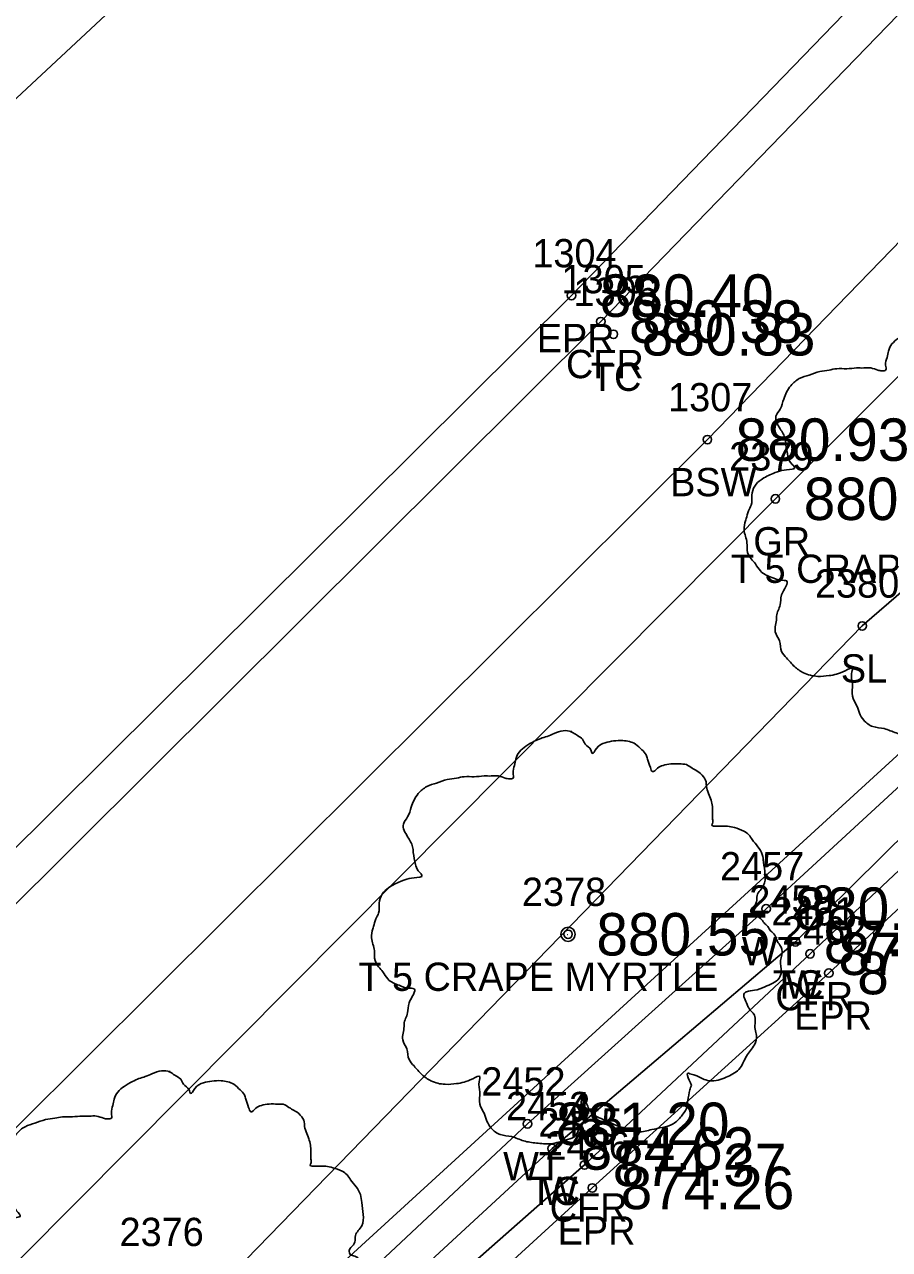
# Model space of a CAD drawing. Extents: x 1622501 to 1626664, y 1117816 to 1121579.
# Drawn here: x 1623704.15 to 1623734.7, y 1118952.01 to 1118995.3 of the extents above; entities that cross this region are included whole.
import ezdxf

# ---------------------------------------------------------------- set-up
doc = ezdxf.new("R2010")
doc.units = 0
for name, color, linetype in [('RD_EX_BldgApp', 7, 'Continuous'), ('RD_EX_Conc', 7, 'Continuous'), ('RD_EX_Conc_txCode', 7, 'Continuous'), ('RD_EX_Fence_Other', 7, 'Continuous'), ('RD_EX_GuardRail', 7, 'Continuous'), ('RD_EX_GuardRail_txCode', 7, 'Continuous'), ('RD_EX_Misc', 7, 'Continuous'), ('RD_EX_Misc_txCode', 7, 'Continuous'), ('RD_EX_Road', 7, 'Continuous'), ('RD_EX_Road_txCode', 7, 'Continuous'), ('RD_EX_TX_Conc_ELEV', 7, 'Continuous'), ('RD_EX_TX_GuardRail_ELEV', 7, 'Continuous'), ('RD_EX_TX_Misc_ELEV', 7, 'Continuous'), ('RD_EX_TX_Road_ELEV', 7, 'Continuous'), ('RD_EX_TX_VEG_ELEV', 7, 'Continuous'), ('RD_EX_VEG', 7, 'Continuous'), ('RD_EX_VEG_txCode', 7, 'Continuous'), ('RD_HC_Cl', 7, 'Continuous'), ('RD_SMD_Locator', 7, 'Continuous')]:
    doc.layers.add(name, color=color, linetype=linetype)

msp = doc.modelspace()

# ---------------------------------------------------------------- linework, layer by layer
at = {"layer": 'RD_EX_BldgApp'}
msp.add_lwpolyline([(1623721.004, 1118923.881), (1623713.492, 1118931.399), (1623708.579, 1118936.802), (1623708.092, 1118940.743), (1623709.133, 1118942.964), (1623722.787, 1118955.582), (1623731.375, 1118962.881), (1623739.462, 1118970.878), (1623747.819, 1118978.398), (1623756.721, 1118986.256), (1623762.191, 1118991.565), (1623766.243, 1118995.292)], dxfattribs=at)
at = {"layer": 'RD_EX_Conc'}
for points in [[(1623723.663, 1118851.276), (1623685.686, 1118891.781), (1623680.278, 1118899.276), (1623678.543, 1118902.667), (1623678.543, 1118902.667), (1623675.573, 1118911.952), (1623675.054, 1118920.354), (1623676.566, 1118930.331), (1623679.225, 1118937.184), (1623684.435, 1118944.641), (1623689.976, 1118950.418), (1623724.501, 1118984.8), (1623759.009, 1119020.42), (1623793.698, 1119055.906), (1623829.35, 1119090.862), (1623865.612, 1119125.129), (1623901.916, 1119159.181), (1623933.224, 1119188.498)], [(1623676.299, 1118912.014), (1623681.213, 1118913.011), (1623680.576, 1118920.41), (1623681.86, 1118928.773), (1623684.243, 1118934.734), (1623688.548, 1118940.788), (1623694.147, 1118946.67), (1623728.265, 1118980.628), (1623762.622, 1119016.068), (1623797.565, 1119051.919), (1623833.104, 1119086.631), (1623869.148, 1119120.8), (1623905.547, 1119154.999), (1623936.969, 1119184.346), (1623933.79, 1119188.026)], [(1623731.27, 1118881.874), (1623724.208, 1118889.844), (1623728.268, 1118894.109), (1623731.921, 1118899.236), (1623734.19, 1118906.762), (1623732.955, 1118915.502), (1623727.506, 1118923.921), (1623710.242, 1118942.93), (1623723.924, 1118955.001), (1623731.892, 1118962.462), (1623739.934, 1118970.016), (1623748.093, 1118977.566), (1623756.653, 1118985.283), (1623766.427, 1118974.182), (1623768.958, 1118972.879), (1623771.85, 1118973.67), (1623773.97, 1118975.964), (1623773.97, 1118975.964), (1623773.559, 1118979.96), (1623763.52, 1118991.319), (1623776.374, 1119003.735), (1623808.841, 1119034.289)]]:
    msp.add_lwpolyline(points, dxfattribs=at)
at = {"layer": 'RD_EX_Fence_Other'}
msp.add_lwpolyline([(1623719.865, 1118922.561), (1623707.713, 1118935.278), (1623705.87, 1118941.129), (1623709.567, 1118946.223), (1623737.438, 1118971.731), (1623764.682, 1118996.227)], dxfattribs=at)
at = {"layer": 'RD_EX_GuardRail'}
msp.add_lwpolyline([(1623683.102, 1118919.005), (1623685.557, 1118930.82), (1623696.428, 1118944.075), (1623730.666, 1118978.537), (1623766.322, 1119014.094)], dxfattribs=at)
at = {"layer": 'RD_EX_Misc'}
msp.add_lwpolyline([(1623720.394, 1118923.404), (1623713.005, 1118930.814), (1623708.177, 1118936.136), (1623707.246, 1118941.456), (1623708.502, 1118943.888), (1623721.912, 1118956.453), (1623730.341, 1118964.055), (1623738.647, 1118971.704), (1623746.964, 1118979.27), (1623755.423, 1118986.8), (1623761.506, 1118992.463), (1623765.64, 1118996.049)], dxfattribs=at)
at = {"layer": 'RD_EX_Road'}
for points in [[(1623722.97, 1118850.612), (1623684.945, 1118891.225), (1623679.413, 1118898.675), (1623674.261, 1118911.526), (1623673.503, 1118920.185), (1623675.206, 1118930.826), (1623677.985, 1118937.822), (1623683.61, 1118945.518), (1623688.806, 1118951.265), (1623723.469, 1118985.717), (1623758.003, 1119021.43), (1623792.693, 1119056.92), (1623828.408, 1119091.915), (1623864.599, 1119126.191), (1623900.882, 1119160.216), (1623932.37, 1119189.416), (1623932.628, 1119189.219), (1623935.818, 1119192.17), (1623973.771, 1119227.767), (1623990.875, 1119243.538), (1624009.987, 1119262.018), (1624046.295, 1119296.153)], [(1623731.855, 1118882.514), (1623725.132, 1118889.887), (1623728.967, 1118893.472), (1623732.76, 1118898.859), (1623735.001, 1118906.68), (1623733.773, 1118915.823), (1623728.206, 1118924.533), (1623711.71, 1118942.753), (1623724.203, 1118954.188), (1623732.557, 1118961.78), (1623740.615, 1118969.244), (1623748.717, 1118976.672), (1623756.637, 1118984.034), (1623765.77, 1118973.634), (1623768.775, 1118971.978), (1623773.17, 1118972.305), (1623775.58, 1118974.356), (1623774.206, 1118980.477), (1623764.618, 1118991.256), (1623776.805, 1119003.039), (1623808.744, 1119033.096)]]:
    msp.add_lwpolyline(points, dxfattribs=at)
at = {"layer": 'RD_EX_VEG'}
msp.add_lwpolyline([(1623719.641, 1118895.843), (1623705.963, 1118915.58), (1623701.704, 1118941.089), (1623733.735, 1118974.045), (1623762.596, 1118998.968), (1623764.149, 1118997.606), (1623773.667, 1119008.214), (1623809.616, 1119040.562), (1623866.904, 1119093.207), (1623868.266, 1119096.09), (1623881.794, 1119107.882), (1623919.645, 1119143.849), (1623945.126, 1119165.729), (1623961.583, 1119122.835), (1623970.119, 1119088.038)], dxfattribs=at)
for centre, radius in [((1623723.346, 1118963.151), 0.25), ((1623723.334, 1118963.133), 0.0001)]:
    msp.add_circle(centre, radius, dxfattribs=at)
for points in [[(1623736.635, 1118984.735), (1623736.335, 1118984.76), (1623736.01, 1118984.66), (1623735.76, 1118984.56), (1623735.535, 1118984.485), (1623735.31, 1118984.385), (1623735.01, 1118984.21), (1623734.785, 1118984.01), (1623734.66, 1118983.76), (1623734.61, 1118983.535), (1623734.561, 1118983.26), (1623734.561, 1118983.085), (1623734.436, 1118983.06), (1623734.286, 1118983.085), (1623734.036, 1118983.16), (1623733.786, 1118983.16), (1623733.536, 1118983.16), (1623733.186, 1118983.135), (1623732.836, 1118983.135), (1623732.561, 1118983.085), (1623732.237, 1118983.035), (1623731.862, 1118982.91), (1623731.512, 1118982.785), (1623731.212, 1118982.535), (1623730.962, 1118982.061), (1623730.837, 1118981.711), (1623730.687, 1118981.461), (1623730.837, 1118981.011), (1623731.012, 1118980.661), (1623731.037, 1118980.461), (1623731.112, 1118980.037), (1623731.212, 1118979.812), (1623731.337, 1118979.612), (1623731.262, 1118979.587), (1623730.887, 1118979.537), (1623730.587, 1118979.437), (1623730.162, 1118979.212), (1623729.938, 1118978.987), (1623729.838, 1118978.662), (1623729.813, 1118978.312), (1623729.713, 1118978.112), (1623729.638, 1118977.838), (1623729.613, 1118977.763), (1623729.563, 1118977.438), (1623729.663, 1118976.988), (1623729.688, 1118976.638), (1623729.813, 1118976.413), (1623729.963, 1118976.238), (1623730.137, 1118975.988), (1623730.537, 1118975.763), (1623730.862, 1118975.663), (1623731.062, 1118975.639), (1623730.887, 1118975.139), (1623730.837, 1118974.789), (1623730.712, 1118974.389), (1623730.712, 1118974.314), (1623730.662, 1118973.839), (1623730.812, 1118973.514), (1623730.887, 1118973.14), (1623731.062, 1118972.915), (1623731.337, 1118972.615), (1623731.662, 1118972.39), (1623732.162, 1118972.265), (1623732.561, 1118972.29), (1623733.136, 1118972.465), (1623733.386, 1118972.54), (1623733.361, 1118972.365), (1623733.386, 1118971.99), (1623733.386, 1118971.565), (1623733.536, 1118971.24), (1623733.636, 1118970.966), (1623733.786, 1118970.716), (1623734.111, 1118970.491), (1623734.511, 1118970.416), (1623734.935, 1118970.266), (1623735.385, 1118970.191), (1623735.885, 1118970.166), (1623736.485, 1118970.316), (1623736.76, 1118970.441), (1623736.86, 1118970.616), (1623737.059, 1118970.991), (1623737.009, 1118971.215), (1623737.034, 1118971.815), (1623737.134, 1118971.64), (1623737.309, 1118971.29), (1623737.809, 1118970.991), (1623738.209, 1118970.816), (1623738.684, 1118970.666), (1623738.984, 1118970.591), (1623739.458, 1118970.666), (1623739.833, 1118970.741), (1623740.208, 1118970.866), (1623740.508, 1118971.14), (1623740.683, 1118971.415), (1623740.733, 1118971.69), (1623740.808, 1118972.065), (1623740.858, 1118972.24)], [(1623723.478, 1118970.319), (1623723.178, 1118970.344), (1623722.853, 1118970.244), (1623722.604, 1118970.144), (1623722.379, 1118970.069), (1623722.154, 1118969.969), (1623721.854, 1118969.794), (1623721.629, 1118969.594), (1623721.504, 1118969.344), (1623721.454, 1118969.119), (1623721.404, 1118968.844), (1623721.404, 1118968.669), (1623721.279, 1118968.644), (1623721.129, 1118968.669), (1623720.879, 1118968.744), (1623720.629, 1118968.744), (1623720.379, 1118968.744), (1623720.03, 1118968.719), (1623719.68, 1118968.719), (1623719.405, 1118968.669), (1623719.08, 1118968.619), (1623718.705, 1118968.494), (1623718.355, 1118968.369), (1623718.056, 1118968.12), (1623717.806, 1118967.645), (1623717.681, 1118967.295), (1623717.531, 1118967.045), (1623717.681, 1118966.595), (1623717.856, 1118966.245), (1623717.881, 1118966.045), (1623717.956, 1118965.621), (1623718.056, 1118965.396), (1623718.18, 1118965.196), (1623718.106, 1118965.171), (1623717.731, 1118965.121), (1623717.431, 1118965.021), (1623717.006, 1118964.796), (1623716.781, 1118964.571), (1623716.681, 1118964.246), (1623716.656, 1118963.896), (1623716.556, 1118963.697), (1623716.481, 1118963.422), (1623716.456, 1118963.347), (1623716.406, 1118963.022), (1623716.506, 1118962.572), (1623716.531, 1118962.222), (1623716.656, 1118961.997), (1623716.806, 1118961.822), (1623716.981, 1118961.572), (1623717.381, 1118961.348), (1623717.706, 1118961.248), (1623717.906, 1118961.223), (1623717.731, 1118960.723), (1623717.681, 1118960.373), (1623717.556, 1118959.973), (1623717.556, 1118959.898), (1623717.506, 1118959.423), (1623717.656, 1118959.098), (1623717.731, 1118958.724), (1623717.906, 1118958.499), (1623718.18, 1118958.199), (1623718.505, 1118957.974), (1623719.005, 1118957.849), (1623719.405, 1118957.874), (1623719.98, 1118958.049), (1623720.23, 1118958.124), (1623720.205, 1118957.949), (1623720.23, 1118957.574), (1623720.23, 1118957.149), (1623720.379, 1118956.825), (1623720.479, 1118956.55), (1623720.629, 1118956.3), (1623720.954, 1118956.075), (1623721.354, 1118956), (1623721.779, 1118955.85), (1623722.229, 1118955.775), (1623722.728, 1118955.75), (1623723.328, 1118955.9), (1623723.603, 1118956.025), (1623723.703, 1118956.2), (1623723.903, 1118956.575), (1623723.853, 1118956.8), (1623723.878, 1118957.399), (1623723.978, 1118957.224), (1623724.153, 1118956.874), (1623724.653, 1118956.575), (1623725.052, 1118956.4), (1623725.527, 1118956.25), (1623725.827, 1118956.175), (1623726.302, 1118956.25), (1623726.677, 1118956.325), (1623727.052, 1118956.45), (1623727.351, 1118956.725), (1623727.526, 1118956.999), (1623727.576, 1118957.274), (1623727.651, 1118957.649), (1623727.701, 1118957.824)], [(1623727.701, 1118957.824), (1623727.626, 1118957.999), (1623727.576, 1118958.249), (1623727.651, 1118958.224), (1623727.826, 1118958.174), (1623728.101, 1118958.049), (1623728.326, 1118957.974), (1623728.651, 1118957.999), (1623728.926, 1118958.099), (1623729.376, 1118958.374), (1623729.65, 1118958.849), (1623729.925, 1118959.248), (1623730, 1118959.573), (1623729.95, 1118959.798), (1623729.925, 1118960.298), (1623729.725, 1118960.548), (1623729.675, 1118960.673), (1623729.575, 1118961.073), (1623729.65, 1118961.123), (1623729.925, 1118961.173), (1623730.3, 1118961.298), (1623730.575, 1118961.422), (1623730.8, 1118961.597), (1623730.875, 1118961.822), (1623730.85, 1118962.222), (1623730.9, 1118962.622), (1623730.825, 1118962.772), (1623730.725, 1118962.922), (1623730.65, 1118963.122), (1623730.5, 1118963.272), (1623730.4, 1118963.422), (1623730.3, 1118963.522), (1623730.175, 1118963.672), (1623730, 1118963.796), (1623729.85, 1118963.846), (1623729.8, 1118963.996), (1623729.95, 1118964.196), (1623730, 1118964.296), (1623730.025, 1118964.521), (1623730.25, 1118964.871), (1623730.3, 1118965.271), (1623730.25, 1118965.696), (1623730.2, 1118965.971), (1623730.05, 1118966.245), (1623729.85, 1118966.495), (1623729.725, 1118966.67), (1623729.55, 1118966.795), (1623729.226, 1118966.92), (1623728.976, 1118966.97), (1623728.626, 1118966.97), (1623728.426, 1118967.02), (1623728.451, 1118967.07), (1623728.451, 1118967.22), (1623728.451, 1118967.495), (1623728.376, 1118967.945), (1623728.226, 1118968.444), (1623728.226, 1118968.469), (1623728.126, 1118968.719), (1623727.901, 1118968.919), (1623727.726, 1118969.019), (1623727.526, 1118969.144), (1623727.276, 1118969.169), (1623726.977, 1118969.169), (1623726.702, 1118969.119), (1623726.502, 1118969.019), (1623726.327, 1118968.894), (1623726.252, 1118969.044), (1623726.152, 1118969.344), (1623726.102, 1118969.494), (1623725.952, 1118969.669), (1623725.727, 1118969.869), (1623725.277, 1118969.994), (1623724.653, 1118969.919), (1623724.353, 1118969.719), (1623724.203, 1118969.544), (1623724.153, 1118969.669), (1623723.953, 1118969.869), (1623723.853, 1118970.044), (1623723.678, 1118970.169), (1623723.528, 1118970.269), (1623723.428, 1118970.319)], [(1623709.292, 1118958.301), (1623708.992, 1118958.326), (1623708.668, 1118958.226), (1623708.418, 1118958.126), (1623708.193, 1118958.051), (1623707.968, 1118957.951), (1623707.668, 1118957.776), (1623707.443, 1118957.576), (1623707.318, 1118957.326), (1623707.268, 1118957.102), (1623707.218, 1118956.827), (1623707.218, 1118956.652), (1623707.093, 1118956.627), (1623706.943, 1118956.652), (1623706.693, 1118956.727), (1623706.444, 1118956.727), (1623706.194, 1118956.727), (1623705.844, 1118956.702), (1623705.494, 1118956.702), (1623705.219, 1118956.652), (1623704.894, 1118956.602), (1623704.519, 1118956.477), (1623704.17, 1118956.352), (1623703.87, 1118956.102), (1623703.62, 1118955.627), (1623703.495, 1118955.277), (1623703.345, 1118955.027), (1623703.495, 1118954.578), (1623703.67, 1118954.228), (1623703.695, 1118954.028), (1623703.77, 1118953.603), (1623703.87, 1118953.378), (1623703.995, 1118953.178), (1623703.92, 1118953.153), (1623703.545, 1118953.103), (1623703.245, 1118953.003), (1623702.82, 1118952.778), (1623702.595, 1118952.554), (1623702.495, 1118952.229), (1623702.47, 1118951.879), (1623702.37, 1118951.679), (1623702.295, 1118951.404), (1623702.27, 1118951.329), (1623702.22, 1118951.004), (1623702.32, 1118950.554), (1623702.345, 1118950.205), (1623702.47, 1118949.98), (1623702.62, 1118949.805), (1623702.795, 1118949.555), (1623703.195, 1118949.33), (1623703.52, 1118949.23), (1623703.72, 1118949.205), (1623703.545, 1118948.705), (1623703.495, 1118948.355), (1623703.37, 1118947.956), (1623703.37, 1118947.881), (1623703.32, 1118947.406), (1623703.47, 1118947.081), (1623703.545, 1118946.706), (1623703.72, 1118946.481), (1623703.995, 1118946.181), (1623704.319, 1118945.956), (1623704.819, 1118945.831), (1623705.219, 1118945.856), (1623705.794, 1118946.031), (1623706.044, 1118946.106), (1623706.019, 1118945.931), (1623706.044, 1118945.557), (1623706.044, 1118945.132), (1623706.194, 1118944.807), (1623706.294, 1118944.532), (1623706.444, 1118944.282), (1623706.768, 1118944.057), (1623707.168, 1118943.982), (1623707.593, 1118943.832), (1623708.043, 1118943.757), (1623708.543, 1118943.732), (1623709.142, 1118943.882), (1623709.417, 1118944.007), (1623709.517, 1118944.182), (1623709.717, 1118944.557), (1623709.667, 1118944.782), (1623709.692, 1118945.382), (1623709.792, 1118945.207), (1623709.967, 1118944.857), (1623710.467, 1118944.557), (1623710.867, 1118944.382), (1623711.341, 1118944.232), (1623711.641, 1118944.157), (1623712.116, 1118944.232), (1623712.491, 1118944.307), (1623712.866, 1118944.432), (1623713.166, 1118944.707), (1623713.341, 1118944.982), (1623713.391, 1118945.257), (1623713.465, 1118945.632), (1623713.515, 1118945.806)], [(1623713.515, 1118945.806), (1623713.441, 1118945.981), (1623713.391, 1118946.231), (1623713.465, 1118946.206), (1623713.64, 1118946.156), (1623713.915, 1118946.031), (1623714.14, 1118945.956), (1623714.465, 1118945.981), (1623714.74, 1118946.081), (1623715.19, 1118946.356), (1623715.465, 1118946.831), (1623715.739, 1118947.231), (1623715.814, 1118947.556), (1623715.764, 1118947.781), (1623715.739, 1118948.28), (1623715.54, 1118948.53), (1623715.49, 1118948.655), (1623715.39, 1118949.055), (1623715.465, 1118949.105), (1623715.739, 1118949.155), (1623716.114, 1118949.28), (1623716.389, 1118949.405), (1623716.614, 1118949.58), (1623716.689, 1118949.805), (1623716.664, 1118950.205), (1623716.714, 1118950.604), (1623716.639, 1118950.754), (1623716.539, 1118950.904), (1623716.464, 1118951.104), (1623716.314, 1118951.254), (1623716.214, 1118951.404), (1623716.114, 1118951.504), (1623715.989, 1118951.654), (1623715.814, 1118951.779), (1623715.665, 1118951.829), (1623715.615, 1118951.979), (1623715.764, 1118952.179), (1623715.814, 1118952.279), (1623715.839, 1118952.504), (1623716.064, 1118952.853), (1623716.114, 1118953.253), (1623716.064, 1118953.678), (1623716.014, 1118953.953), (1623715.864, 1118954.228), (1623715.665, 1118954.478), (1623715.54, 1118954.653), (1623715.365, 1118954.778), (1623715.04, 1118954.903), (1623714.79, 1118954.952), (1623714.44, 1118954.952), (1623714.24, 1118955.002), (1623714.265, 1118955.052), (1623714.265, 1118955.202), (1623714.265, 1118955.477), (1623714.19, 1118955.927), (1623714.04, 1118956.427), (1623714.04, 1118956.452), (1623713.94, 1118956.702), (1623713.715, 1118956.902), (1623713.54, 1118957.002), (1623713.341, 1118957.127), (1623713.091, 1118957.152), (1623712.791, 1118957.152), (1623712.516, 1118957.102), (1623712.316, 1118957.002), (1623712.141, 1118956.877), (1623712.066, 1118957.027), (1623711.966, 1118957.326), (1623711.916, 1118957.476), (1623711.766, 1118957.651), (1623711.541, 1118957.851), (1623711.091, 1118957.976), (1623710.467, 1118957.901), (1623710.167, 1118957.701), (1623710.017, 1118957.526), (1623709.967, 1118957.651), (1623709.767, 1118957.851), (1623709.667, 1118958.026), (1623709.492, 1118958.151), (1623709.342, 1118958.251), (1623709.242, 1118958.301)]]:
    msp.add_spline(points, degree=3, dxfattribs=at)
at = {"layer": 'RD_HC_Cl'}
msp.add_line((1623608.837, 1118904.32), (1623937.248, 1119209.793), dxfattribs=at)
at = {"layer": 'RD_SMD_Locator'}
for centre in [(1623723.469, 1118985.717), (1623724.501, 1118984.8), (1623724.946, 1118984.351), (1623728.265, 1118980.628), (1623730.666, 1118978.537), (1623733.735, 1118974.045), (1623730.341, 1118964.055), (1623723.346, 1118963.151), (1623731.375, 1118962.881), (1623731.375, 1118962.881), (1623731.892, 1118962.462), (1623732.557, 1118961.78), (1623721.912, 1118956.453), (1623722.787, 1118955.582), (1623722.787, 1118955.582), (1623723.924, 1118955.001), (1623724.203, 1118954.188)]:
    msp.add_circle(centre, 0.15, dxfattribs=at)

# ---------------------------------------------------------------- texts
at = {"layer": 'RD_EX_Conc_txCode'}
for s, p in [('1305', (1623723.115, 1118985.8)), ('1306', (1623723.537, 1118985.351)), ('CFR', (1623723.272, 1118982.8)), ('TC', (1623724.151, 1118982.351)), ('1307', (1623726.879, 1118981.628)), ('BSW', (1623726.95, 1118978.628)), ('2459', (1623729.745, 1118963.881)), ('2461', (1623730.522, 1118963.462)), ('TC', (1623730.58, 1118960.881)), ('CFR', (1623730.664, 1118960.462)), ('2454', (1623721.157, 1118956.582)), ('2455', (1623722.294, 1118956.001)), ('TC', (1623721.991, 1118953.582)), ('CFR', (1623722.695, 1118953.001))]:
    msp.add_text(s, height=1, dxfattribs=at).set_placement(p)
at = {"layer": 'RD_EX_GuardRail_txCode'}
for s, p in [('2379', (1623729.036, 1118979.537)), ('GR', (1623729.887, 1118976.537))]:
    msp.add_text(s, height=1, dxfattribs=at).set_placement(p)
at = {"layer": 'RD_EX_Misc_txCode'}
for s, p in [('2457', (1623728.711, 1118965.055)), ('2458', (1623729.745, 1118963.881)), ('WT', (1623729.483, 1118962.055)), ('W', (1623731.005, 1118960.881)), ('2452', (1623720.282, 1118957.453)), ('2453', (1623721.157, 1118956.582)), ('WT', (1623721.054, 1118954.453)), ('W', (1623722.416, 1118953.582))]:
    msp.add_text(s, height=1, dxfattribs=at).set_placement(p)
at = {"layer": 'RD_EX_Road_txCode'}
for s, p in [('1304', (1623722.083, 1118986.717)), ('EPR', (1623722.24, 1118983.717)), ('2462', (1623730.903, 1118962.78)), ('EPR', (1623731.329, 1118959.78)), ('2456', (1623722.549, 1118955.188)), ('EPR', (1623722.975, 1118952.188))]:
    msp.add_text(s, height=1, dxfattribs=at).set_placement(p)
at = {"layer": 'RD_EX_TX_Conc_ELEV'}
for s, p in [('880.38', (1623725.501, 1118984.05)), ('880.83', (1623725.946, 1118983.601)), ('880.93', (1623729.265, 1118979.878)), ('874.51', (1623732.375, 1118962.131)), ('874.07', (1623732.892, 1118961.712)), ('874.62', (1623723.787, 1118954.832)), ('874.37', (1623724.924, 1118954.251))]:
    msp.add_text(s, height=1.5, dxfattribs=at).set_placement(p)
at = {"layer": 'RD_EX_TX_GuardRail_ELEV'}
msp.add_text('880.42', height=1.5, dxfattribs=at).set_placement((1623731.666, 1118977.787))
at = {"layer": 'RD_EX_TX_Misc_ELEV'}
for s, p in [('880.59', (1623731.341, 1118963.305)), ('874.51', (1623732.375, 1118962.131)), ('881.20', (1623722.912, 1118955.703)), ('874.62', (1623723.787, 1118954.832))]:
    msp.add_text(s, height=1.5, dxfattribs=at).set_placement(p)
at = {"layer": 'RD_EX_TX_Road_ELEV'}
for s, p in [('880.40', (1623724.469, 1118984.967)), ('874.07', (1623733.557, 1118961.03)), ('874.26', (1623725.203, 1118953.438))]:
    msp.add_text(s, height=1.5, dxfattribs=at).set_placement(p)
at = {"layer": 'RD_EX_TX_VEG_ELEV'}
msp.add_text('880.55', height=1.5, dxfattribs=at).set_placement((1623724.346, 1118962.401))
at = {"layer": 'RD_EX_VEG_txCode'}
for s, p in [('T 5 CRAPE MYRTLE', (1623729.097, 1118975.567)), ('2380', (1623732.066, 1118975.045)), ('SL', (1623732.979, 1118972.045)), ('2378', (1623721.716, 1118964.151)), ('T 5 CRAPE MYRTLE', (1623715.941, 1118961.151)), ('2376', (1623707.507, 1118952.134))]:
    msp.add_text(s, height=1, dxfattribs=at).set_placement(p)

doc.saveas('drawing.dxf')
